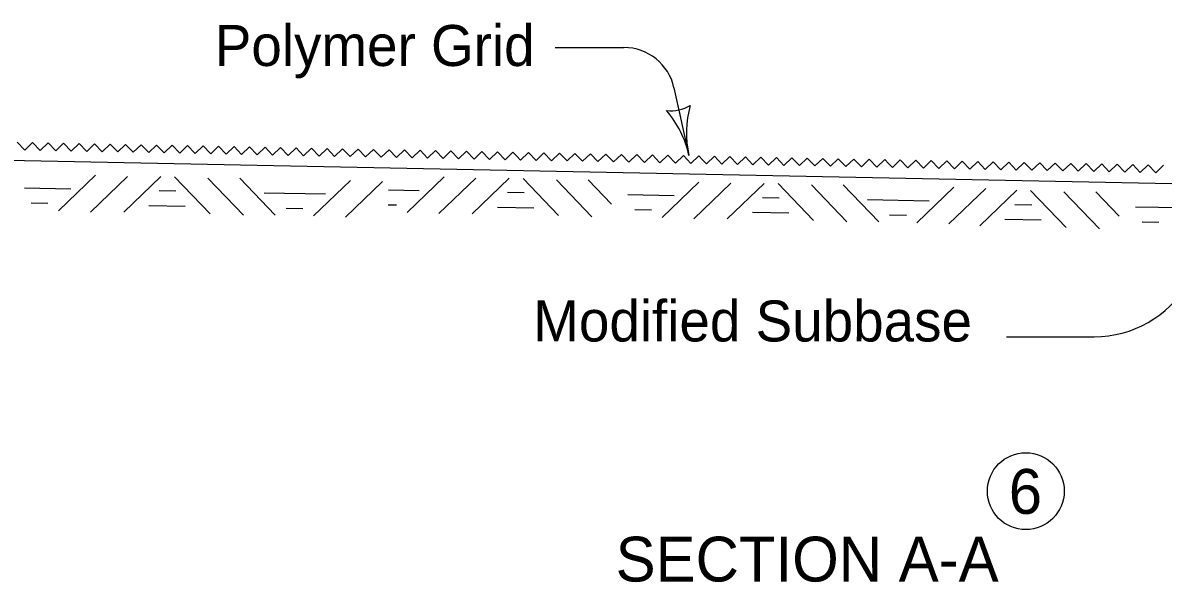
# Model space of a CAD drawing. Extents: x -2134934 to -2124557, y -2139046 to -2134021.
# Drawn here: x -2127477.9 to -2127032.7, y -2137530.3 to -2137312 of the extents above; entities that cross this region are included whole.
import ezdxf

# ---------------------------------------------------------------- set-up
doc = ezdxf.new("R2010")
doc.units = 0
doc.layers.add('BridgeSuperStructureExisting', color=7, linetype='Continuous')
doc.layers.add('dsnStdLabel', color=7, linetype='Continuous')

msp = doc.modelspace()

# ---------------------------------------------------------------- linework, layer by layer
at = {"layer": 'BridgeSuperStructureExisting'}
for p, q in [((-2127269.99, -2137321.68), (-2127243.18, -2137321.68)), ((-2127223.65, -2137337.38), (-2127217.83, -2137363.75)), ((-2127222.22, -2137343.83), (-2127221.1, -2137348.94)), ((-2127483.71, -2137365.58), (-2126667.12, -2137381.97)), ((-2127449.49, -2137371.53), (-2127463.91, -2137385.38)), ((-2127437.04, -2137372), (-2127451.47, -2137385.86)), ((-2127424.03, -2137372.04), (-2127438.46, -2137385.89)), ((-2127418.62, -2137372.15), (-2127404.77, -2137386.57)), ((-2127405.62, -2137372.63), (-2127391.77, -2137387.06)), ((-2127393.17, -2137372.66), (-2127379.31, -2137387.08)), ((-2127349.95, -2137373.52), (-2127364.38, -2137387.38)), ((-2127337.51, -2137374), (-2127351.93, -2137387.85)), ((-2127313.42, -2137372.17), (-2127327.84, -2137386.02)), ((-2127300.97, -2137372.64), (-2127315.4, -2137386.5)), ((-2127287.96, -2137372.68), (-2127302.39, -2137386.53)), ((-2127282.55, -2137372.78), (-2127268.7, -2137387.21)), ((-2127269.55, -2137373.27), (-2127255.7, -2137387.69)), ((-2127257.1, -2137373.3), (-2127248, -2137382.77)), ((-2127213.89, -2137374.16), (-2127228.31, -2137388.02)), ((-2127201.44, -2137374.64), (-2127215.87, -2137388.49)), ((-2127188.43, -2137374.67), (-2127202.86, -2137388.53)), ((-2127183.02, -2137374.78), (-2127169.17, -2137389.21)), ((-2127170.02, -2137375.27), (-2127156.17, -2137389.69)), ((-2127157.57, -2137375.29), (-2127143.71, -2137389.72)), ((-2127114.35, -2137376.16), (-2127128.78, -2137390.02)), ((-2127101.91, -2137376.64), (-2127116.33, -2137390.49)), ((-2127089.86, -2137377.39), (-2127104.28, -2137391.25)), ((-2127084.45, -2137377.5), (-2127070.6, -2137391.92)), ((-2127071.45, -2137377.99), (-2127057.59, -2137392.41)), ((-2127059, -2137378.01), (-2127049.9, -2137387.49)), ((-2127093.85, -2137434.51), (-2127059.57, -2137434.51))]:
    msp.add_line(p, q, dxfattribs=at)
for points in [[(-2127480.08, -2137358.61), (-2127477.12, -2137361.7), (-2127474.03, -2137358.74), (-2127471.07, -2137361.82), (-2127467.98, -2137358.86), (-2127465.02, -2137361.95), (-2127461.94, -2137358.98), (-2127458.97, -2137362.07), (-2127455.89, -2137359.1), (-2127452.92, -2137362.18), (-2127449.84, -2137359.22), (-2127446.87, -2137362.31), (-2127443.79, -2137359.35), (-2127440.83, -2137362.43), (-2127437.74, -2137359.47), (-2127434.78, -2137362.55), (-2127431.69, -2137359.58), (-2127430.21, -2137361.13)], [(-2127430.21, -2137361.13), (-2127428.73, -2137362.67), (-2127425.64, -2137359.71), (-2127422.68, -2137362.79), (-2127419.59, -2137359.83), (-2127416.63, -2137362.92), (-2127413.54, -2137359.95), (-2127410.58, -2137363.04), (-2127407.5, -2137360.07), (-2127404.53, -2137363.16), (-2127401.45, -2137360.19), (-2127398.48, -2137363.28), (-2127395.4, -2137360.32), (-2127392.44, -2137363.4), (-2127389.35, -2137360.44), (-2127386.39, -2137363.52), (-2127383.3, -2137360.56), (-2127380.34, -2137363.64), (-2127377.25, -2137360.68), (-2127374.29, -2137363.76), (-2127371.2, -2137360.8), (-2127368.24, -2137363.89), (-2127365.16, -2137360.92), (-2127362.2, -2137364.01), (-2127359.11, -2137361.04), (-2127357.62, -2137362.59)], [(-2127357.62, -2137362.59), (-2127356.15, -2137364.13), (-2127353.06, -2137361.17), (-2127350.09, -2137364.25), (-2127347.01, -2137361.29), (-2127344.04, -2137364.37), (-2127340.96, -2137361.41), (-2127338, -2137364.49), (-2127334.91, -2137361.53), (-2127331.95, -2137364.61), (-2127328.87, -2137361.65), (-2127325.9, -2137364.74), (-2127322.81, -2137361.77), (-2127319.85, -2137364.86), (-2127316.77, -2137361.89), (-2127313.8, -2137364.98), (-2127310.72, -2137362.01), (-2127307.76, -2137365.1), (-2127304.67, -2137362.14), (-2127301.71, -2137365.22), (-2127298.62, -2137362.26), (-2127295.66, -2137365.34), (-2127292.57, -2137362.38), (-2127289.61, -2137365.46), (-2127286.52, -2137362.5), (-2127285.04, -2137364.04)], [(-2127285.04, -2137364.04), (-2127283.56, -2137365.58), (-2127280.48, -2137362.62), (-2127277.51, -2137365.71), (-2127274.43, -2137362.74), (-2127271.46, -2137365.83), (-2127268.38, -2137362.86), (-2127265.41, -2137365.95), (-2127262.33, -2137362.98), (-2127259.37, -2137366.07), (-2127256.28, -2137363.11), (-2127253.32, -2137366.19), (-2127250.23, -2137363.23), (-2127247.27, -2137366.32), (-2127244.18, -2137363.35), (-2127241.22, -2137366.43), (-2127238.13, -2137363.47), (-2127235.17, -2137366.55), (-2127232.09, -2137363.59), (-2127229.12, -2137366.68), (-2127226.04, -2137363.72), (-2127223.07, -2137366.8), (-2127219.99, -2137363.84), (-2127217.02, -2137366.92), (-2127213.94, -2137363.96), (-2127212.46, -2137365.5)], [(-2127212.46, -2137365.5), (-2127210.98, -2137367.04), (-2127207.89, -2137364.08), (-2127204.93, -2137367.16), (-2127201.84, -2137364.2), (-2127198.88, -2137367.29), (-2127195.79, -2137364.32), (-2127192.83, -2137367.41), (-2127189.74, -2137364.44), (-2127186.78, -2137367.53), (-2127183.69, -2137364.56), (-2127180.73, -2137367.65), (-2127177.65, -2137364.69), (-2127174.68, -2137367.77), (-2127171.6, -2137364.81), (-2127168.63, -2137367.89), (-2127165.55, -2137364.93), (-2127162.58, -2137368.01), (-2127159.5, -2137365.05), (-2127156.54, -2137368.13), (-2127153.45, -2137365.17), (-2127150.49, -2137368.26), (-2127147.4, -2137365.29), (-2127144.44, -2137368.38), (-2127141.35, -2137365.41), (-2127139.87, -2137366.96)], [(-2127139.87, -2137366.96), (-2127138.39, -2137368.5), (-2127135.31, -2137365.53), (-2127132.34, -2137368.62), (-2127129.26, -2137365.66), (-2127126.29, -2137368.74), (-2127123.21, -2137365.78), (-2127120.24, -2137368.86), (-2127117.16, -2137365.9), (-2127114.19, -2137368.98), (-2127111.11, -2137366.02), (-2127108.15, -2137369.11), (-2127105.06, -2137366.14), (-2127102.1, -2137369.23), (-2127099.01, -2137366.26), (-2127096.05, -2137369.35), (-2127092.96, -2137366.38), (-2127090, -2137369.47), (-2127086.91, -2137366.51), (-2127083.95, -2137369.59), (-2127080.87, -2137366.63), (-2127077.9, -2137369.71), (-2127074.82, -2137366.75), (-2127071.85, -2137369.83), (-2127068.77, -2137366.87), (-2127067.29, -2137368.41)], [(-2127067.29, -2137368.41), (-2127065.8, -2137369.95), (-2127062.72, -2137366.99), (-2127059.76, -2137370.08), (-2127056.67, -2137367.12), (-2127053.71, -2137370.2), (-2127050.62, -2137367.23), (-2127047.66, -2137370.32), (-2127044.57, -2137367.35), (-2127041.61, -2137370.44), (-2127038.53, -2137367.48), (-2127035.56, -2137370.56), (-2127032.48, -2137367.6)], [(-2127477.24, -2137376.44), (-2127459.18, -2137376.81)], [(-2127424.7, -2137377.52), (-2127418.17, -2137377.65)], [(-2127383.7, -2137378.32), (-2127359.64, -2137378.81)], [(-2127335.13, -2137377.21), (-2127323.11, -2137377.45)], [(-2127288.63, -2137378.16), (-2127282.1, -2137378.29)], [(-2127241.64, -2137379.08), (-2127223.58, -2137379.44)], [(-2127474.59, -2137382.3), (-2127468.06, -2137382.43)], [(-2127428.65, -2137383.3), (-2127414.46, -2137383.59)], [(-2127335.25, -2137383), (-2127331.99, -2137383.07)], [(-2127292.58, -2137383.94), (-2127278.39, -2137384.22)], [(-2127189.1, -2137380.16), (-2127182.57, -2137380.29)], [(-2127148.1, -2137380.96), (-2127124.04, -2137381.44)], [(-2127090.53, -2137382.88), (-2127084, -2137383.01)], [(-2127043.53, -2137383.8), (-2127025.47, -2137384.16)], [(-2127375.05, -2137384.3), (-2127368.52, -2137384.43)], [(-2127238.99, -2137384.94), (-2127232.45, -2137385.07)], [(-2127193.05, -2137385.94), (-2127178.86, -2137386.22)], [(-2127139.45, -2137386.93), (-2127132.92, -2137387.06)], [(-2127094.48, -2137388.66), (-2127080.29, -2137388.94)], [(-2127040.88, -2137389.65), (-2127034.35, -2137389.78)]]:
    msp.add_lwpolyline(points, dxfattribs=at)
msp.add_circle((-2127086.3, -2137494.79), 15, dxfattribs=at)
for centre, radius, start, end in [((-2127243.18, -2137341.68), 20, 12.4314, 90), ((-2127225.08, -2137330.85), 15.52, 264.685, 300.1517), ((-2127257.07, -2137372.39), 40.18, 12.4183, 40.4908), ((-2127178.6, -2137355.11), 40.18, 164.3459, 192.4183), ((-2127059.56, -2137391.97), 42.54, 270, 329.1249)]:
    msp.add_arc(centre, radius, start, end, dxfattribs=at)

# ---------------------------------------------------------------- texts
at = {"layer": 'dsnStdLabel'}
for s, height, p in [('Polymer Grid', 16, (-2127402.92, -2137328.88)), ('Modified Subbase', 16, (-2127278.59, -2137436.38)), ('6', 17.5, (-2127092.95, -2137503.65)), ('SECTION A-A', 17.5, (-2127246.43, -2137530.06))]:
    msp.add_text(s, height=height, dxfattribs=at).set_placement(p)

doc.saveas('drawing.dxf')
